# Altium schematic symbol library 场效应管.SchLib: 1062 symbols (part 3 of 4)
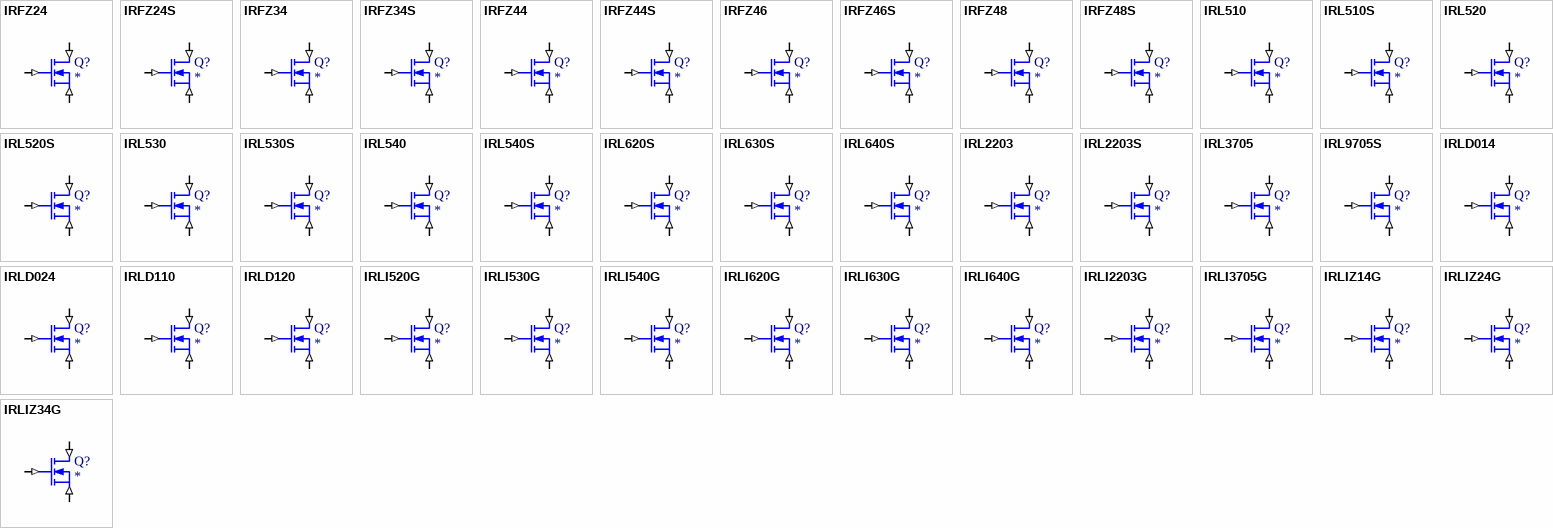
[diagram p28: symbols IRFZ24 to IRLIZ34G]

## IRL630S
designator Q?
N-Channel MOSFET
simulation model IRL630S (SUBCKT)
pins: 1 D (in), 2 G (in), 3 S (in)
1 alternate drawing of the same symbol

## IRL640S
designator Q?
N-Channel MOSFET
simulation model IRL640S (SUBCKT)
pins: 1 D (in), 2 G (in), 3 S (in)
1 alternate drawing of the same symbol

## IRL2203
designator Q?
N-Channel MOSFET
simulation model IRL2203 (SUBCKT)
pins: 1 D (in), 2 G (in), 3 S (in)
1 alternate drawing of the same symbol

## IRL2203S
designator Q?
N-Channel MOSFET
simulation model IRL2203S (SUBCKT)
pins: 1 D (in), 2 G (in), 3 S (in)
1 alternate drawing of the same symbol

## IRL3705
designator Q?
N-Channel MOSFET
simulation model IRL3705 (SUBCKT)
pins: 1 D (in), 2 G (in), 3 S (in)
1 alternate drawing of the same symbol

## IRL9705S
designator Q?
N-Channel MOSFET
simulation model IRL9705S (SUBCKT)
pins: 1 D (in), 2 G (in), 3 S (in)
1 alternate drawing of the same symbol

## IRLD014
designator Q?
N-Channel MOSFET
simulation model IRLD014 (SUBCKT)
pins: 1 D (in), 2 G (in), 3 S (in)
1 alternate drawing of the same symbol

## IRLD024
designator Q?
N-Channel MOSFET
simulation model IRLD024 (SUBCKT)
pins: 1 D (in), 2 G (in), 3 S (in)
1 alternate drawing of the same symbol

## IRLD110
designator Q?
N-Channel MOSFET
simulation model IRLD110 (SUBCKT)
pins: 1 D (in), 2 G (in), 3 S (in)
1 alternate drawing of the same symbol

## IRLD120
designator Q?
N-Channel MOSFET
simulation model IRLD120 (SUBCKT)
pins: 1 D (in), 2 G (in), 3 S (in)
1 alternate drawing of the same symbol

## IRLI520G
designator Q?
N-Channel MOSFET
simulation model IRLI520G (SUBCKT)
pins: 1 D (in), 2 G (in), 3 S (in)
1 alternate drawing of the same symbol

## IRLI530G
designator Q?
N-Channel MOSFET
simulation model IRLI530G (SUBCKT)
pins: 1 D (in), 2 G (in), 3 S (in)
1 alternate drawing of the same symbol

## IRLI540G
designator Q?
N-Channel MOSFET
simulation model IRLI540G (SUBCKT)
pins: 1 D (in), 2 G (in), 3 S (in)
1 alternate drawing of the same symbol

## IRLI620G
designator Q?
N-Channel MOSFET
simulation model IRLI620G (SUBCKT)
pins: 1 D (in), 2 G (in), 3 S (in)
1 alternate drawing of the same symbol

## IRLI630G
designator Q?
N-Channel MOSFET
simulation model IRLI630G (SUBCKT)
pins: 1 D (in), 2 G (in), 3 S (in)
1 alternate drawing of the same symbol

## IRLI640G
designator Q?
N-Channel MOSFET
simulation model IRLI640G (SUBCKT)
pins: 1 D (in), 2 G (in), 3 S (in)
1 alternate drawing of the same symbol

## IRLI2203G
designator Q?
N-Channel MOSFET
simulation model IRLI2203G (SUBCKT)
pins: 1 D (in), 2 G (in), 3 S (in)
1 alternate drawing of the same symbol

## IRLI3705G
designator Q?
N-Channel MOSFET
simulation model IRLI3705G (SUBCKT)
pins: 1 D (in), 2 G (in), 3 S (in)
1 alternate drawing of the same symbol

## IRLIZ14G
designator Q?
N-Channel MOSFET
simulation model IRLIZ14G (SUBCKT)
pins: 1 D (in), 2 G (in), 3 S (in)
1 alternate drawing of the same symbol

## IRLIZ24G
designator Q?
N-Channel MOSFET
simulation model IRLIZ24G (SUBCKT)
pins: 1 D (in), 2 G (in), 3 S (in)
1 alternate drawing of the same symbol

## IRLIZ34G
designator Q?
N-Channel MOSFET
simulation model IRLIZ34G (SUBCKT)
pins: 1 D (in), 2 G (in), 3 S (in)
1 alternate drawing of the same symbol

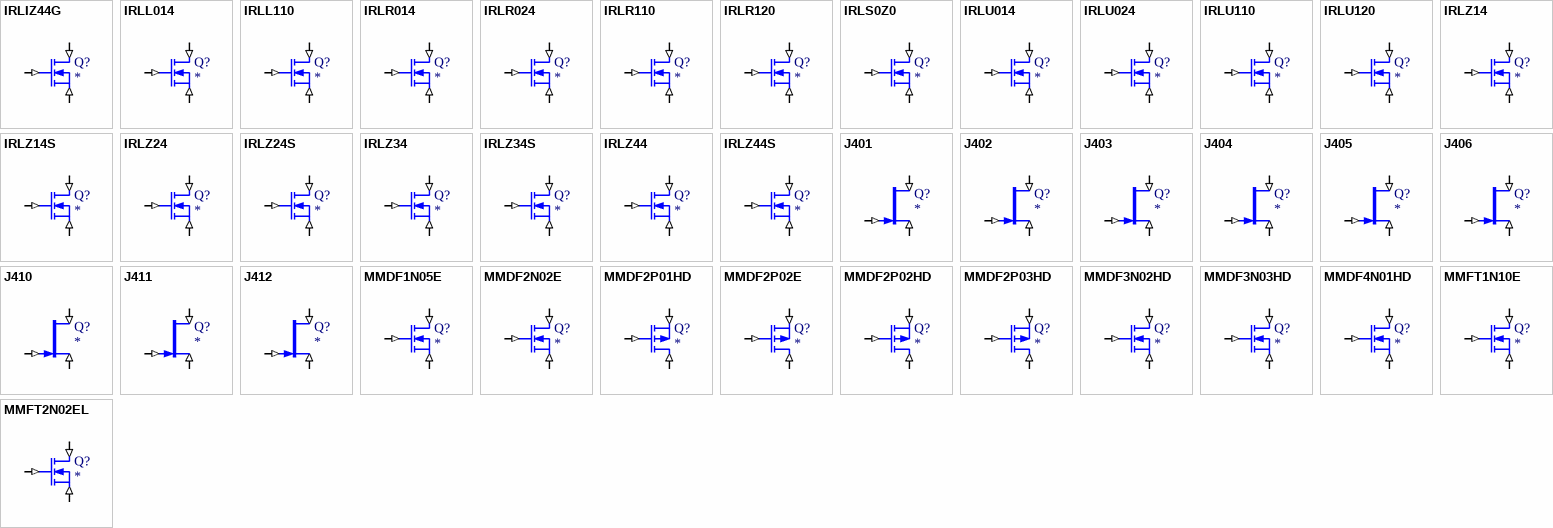
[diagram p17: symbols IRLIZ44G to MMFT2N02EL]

## IRLIZ44G
designator Q?
N-Channel MOSFET
simulation model IRLIZ44G (SUBCKT)
pins: 1 D (in), 2 G (in), 3 S (in)
1 alternate drawing of the same symbol

## IRLL014
designator Q?
N-Channel MOSFET
simulation model IRLL014 (SUBCKT)
pins: 1 D (in), 2 G (in), 3 S (in)
1 alternate drawing of the same symbol

## IRLL110
designator Q?
N-Channel MOSFET
simulation model IRLL110 (SUBCKT)
pins: 1 D (in), 2 G (in), 3 S (in)
1 alternate drawing of the same symbol

## IRLR014
designator Q?
N-Channel MOSFET
simulation model IRLR014 (SUBCKT)
pins: 1 D (in), 2 G (in), 3 S (in)
1 alternate drawing of the same symbol

## IRLR024
designator Q?
N-Channel MOSFET
simulation model IRLR024 (SUBCKT)
pins: 1 D (in), 2 G (in), 3 S (in)
1 alternate drawing of the same symbol

## IRLR110
designator Q?
N-Channel MOSFET
simulation model IRLR110 (SUBCKT)
pins: 1 D (in), 2 G (in), 3 S (in)
1 alternate drawing of the same symbol

## IRLR120
designator Q?
N-Channel MOSFET
simulation model IRLR120 (SUBCKT)
pins: 1 D (in), 2 G (in), 3 S (in)
1 alternate drawing of the same symbol

## IRLS0Z0
designator Q?
N-Channel MOSFET
simulation model IRLS0Z0 (SUBCKT)
pins: 1 D (in), 2 G (in), 3 S (in)
1 alternate drawing of the same symbol

## IRLU014
designator Q?
N-Channel MOSFET
simulation model IRLU014 (SUBCKT)
pins: 1 D (in), 2 G (in), 3 S (in)
1 alternate drawing of the same symbol

## IRLU024
designator Q?
N-Channel MOSFET
simulation model IRLU024 (SUBCKT)
pins: 1 D (in), 2 G (in), 3 S (in)
1 alternate drawing of the same symbol

## IRLU110
designator Q?
N-Channel MOSFET
simulation model IRLU110 (SUBCKT)
pins: 1 D (in), 2 G (in), 3 S (in)
1 alternate drawing of the same symbol

## IRLU120
designator Q?
N-Channel MOSFET
simulation model IRLU120 (SUBCKT)
pins: 1 D (in), 2 G (in), 3 S (in)
1 alternate drawing of the same symbol

## IRLZ14
designator Q?
N-Channel MOSFET
simulation model IRLZ14 (SUBCKT)
pins: 1 D (in), 2 G (in), 3 S (in)
1 alternate drawing of the same symbol

## IRLZ14S
designator Q?
N-Channel MOSFET
simulation model IRLZ14S (SUBCKT)
pins: 1 D (in), 2 G (in), 3 S (in)
1 alternate drawing of the same symbol

## IRLZ24
designator Q?
N-Channel MOSFET
simulation model IRLZ24 (SUBCKT)
pins: 1 D (in), 2 G (in), 3 S (in)
1 alternate drawing of the same symbol

## IRLZ24S
designator Q?
N-Channel MOSFET
simulation model IRLZ24S (SUBCKT)
pins: 1 D (in), 2 G (in), 3 S (in)
1 alternate drawing of the same symbol

## IRLZ34
designator Q?
N-Channel MOSFET
simulation model IRLZ34 (SUBCKT)
pins: 1 D (in), 2 G (in), 3 S (in)
1 alternate drawing of the same symbol

## IRLZ34S
designator Q?
N-Channel MOSFET
simulation model IRLZ34S (SUBCKT)
pins: 1 D (in), 2 G (in), 3 S (in)
1 alternate drawing of the same symbol

## IRLZ44
designator Q?
N-Channel MOSFET
simulation model IRLZ44 (SUBCKT)
pins: 1 D (in), 2 G (in), 3 S (in)
1 alternate drawing of the same symbol

## IRLZ44S
designator Q?
N-Channel MOSFET
simulation model IRLZ44S (SUBCKT)
pins: 1 D (in), 2 G (in), 3 S (in)
1 alternate drawing of the same symbol

## J401
designator Q?
N-Channel JFET
simulation model J401 (NJFET)
pins: 1 D (in), 2 G (in), 3 S (in)
1 alternate drawing of the same symbol

## J402
designator Q?
N-Channel JFET
simulation model J402 (NJFET)
pins: 1 D (in), 2 G (in), 3 S (in)
1 alternate drawing of the same symbol

## J403
designator Q?
N-Channel JFET
simulation model J403 (NJFET)
pins: 1 D (in), 2 G (in), 3 S (in)
1 alternate drawing of the same symbol

## J404
designator Q?
N-Channel JFET
simulation model J404 (NJFET)
pins: 1 D (in), 2 G (in), 3 S (in)
1 alternate drawing of the same symbol

## J405
designator Q?
N-Channel JFET
simulation model J405 (NJFET)
pins: 1 D (in), 2 G (in), 3 S (in)
1 alternate drawing of the same symbol

## J406
designator Q?
N-Channel JFET
simulation model J406 (NJFET)
pins: 1 D (in), 2 G (in), 3 S (in)
1 alternate drawing of the same symbol

## J410
designator Q?
N-Channel JFET
simulation model J410 (NJFET)
pins: 1 D (in), 2 G (in), 3 S (in)
1 alternate drawing of the same symbol

## J411
designator Q?
N-Channel JFET
simulation model J411 (NJFET)
pins: 1 D (in), 2 G (in), 3 S (in)
1 alternate drawing of the same symbol

## J412
designator Q?
N-Channel JFET
simulation model J412 (NJFET)
pins: 1 D (in), 2 G (in), 3 S (in)
1 alternate drawing of the same symbol

## MMDF1N05E
designator Q?
N-Channel MOSFET
simulation model MMDF1N05E (SUBCKT)
pins: 1 D (in), 2 G (in), 3 S (in)
1 alternate drawing of the same symbol

## MMDF2N02E
designator Q?
N-Channel MOSFET
simulation model MMDF2N02E (SUBCKT)
pins: 1 D (in), 2 G (in), 3 S (in)
1 alternate drawing of the same symbol

## MMDF2P01HD
designator Q?
P-Channel MOSFET
simulation model MMDF2P01HD (SUBCKT)
pins: 1 D (in), 2 G (in), 3 S (in)
1 alternate drawing of the same symbol

## MMDF2P02E
designator Q?
P-Channel MOSFET
simulation model MMDF2P02E (SUBCKT)
pins: 1 D (in), 2 G (in), 3 S (in)
1 alternate drawing of the same symbol

## MMDF2P02HD
designator Q?
P-Channel MOSFET
simulation model MMDF2P02HD (SUBCKT)
pins: 1 D (in), 2 G (in), 3 S (in)
1 alternate drawing of the same symbol

## MMDF2P03HD
designator Q?
P-Channel MOSFET
simulation model MMDF2P03HD (SUBCKT)
pins: 1 D (in), 2 G (in), 3 S (in)
1 alternate drawing of the same symbol

## MMDF3N02HD
designator Q?
N-Channel MOSFET
simulation model MMDF3N02HD (SUBCKT)
pins: 1 D (in), 2 G (in), 3 S (in)
1 alternate drawing of the same symbol

## MMDF3N03HD
designator Q?
N-Channel MOSFET
simulation model MMDF3N03HD (SUBCKT)
pins: 1 D (in), 2 G (in), 3 S (in)
1 alternate drawing of the same symbol

## MMDF4N01HD
designator Q?
N-Channel MOSFET
simulation model MMDF4N01HD (SUBCKT)
pins: 1 D (in), 2 G (in), 3 S (in)
1 alternate drawing of the same symbol

## MMFT1N10E
designator Q?
N-Channel MOSFET
simulation model MMFT1N10E (SUBCKT)
pins: 1 D (in), 2 G (in), 3 S (in)
1 alternate drawing of the same symbol

## MMFT2N02EL
designator Q?
N-Channel MOSFET
simulation model MMFT2N02EL (SUBCKT)
pins: 1 D (in), 2 G (in), 3 S (in)
1 alternate drawing of the same symbol

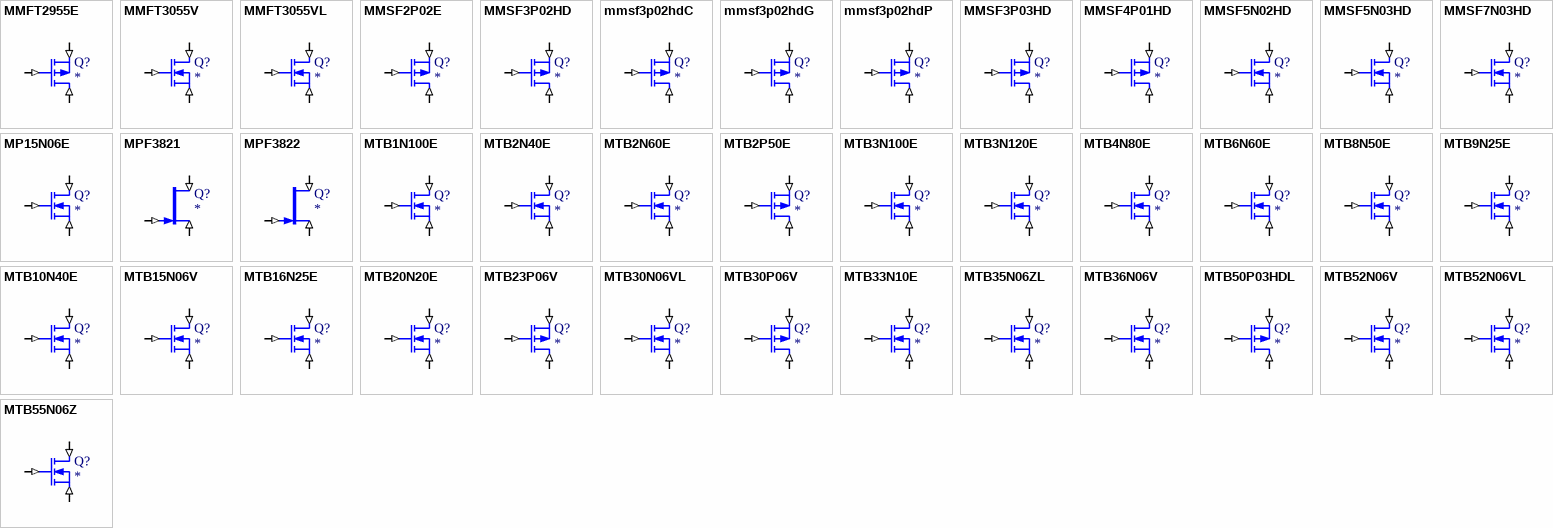
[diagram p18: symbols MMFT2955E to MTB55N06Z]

## MMFT2955E
designator Q?
P-Channel MOSFET
simulation model MMFT2955E (SUBCKT)
pins: 1 D (in), 2 G (in), 3 S (in)
1 alternate drawing of the same symbol

## MMFT3055V
designator Q?
N-Channel MOSFET
simulation model MMFT3055V (SUBCKT)
pins: 1 D (in), 2 G (in), 3 S (in)
1 alternate drawing of the same symbol

## MMFT3055VL
designator Q?
N-Channel MOSFET
simulation model MMFT3055VL (SUBCKT)
pins: 1 D (in), 2 G (in), 3 S (in)
1 alternate drawing of the same symbol

## MMSF2P02E
designator Q?
P-Channel MOSFET
simulation model MMSF2P02E (SUBCKT)
pins: 1 D (in), 2 G (in), 3 S (in)
1 alternate drawing of the same symbol

## MMSF3P02HD
designator Q?
P-Channel MOSFET
simulation model MMSF3P02HD (SUBCKT)
pins: 1 D (in), 2 G (in), 3 S (in)
1 alternate drawing of the same symbol

## mmsf3p02hdC
designator Q?
P-Channel MOSFET
simulation model mmsf3p02hdC (SUBCKT)
pins: 1 D (in), 2 G (in), 3 S (in)
1 alternate drawing of the same symbol

## mmsf3p02hdG
designator Q?
P-Channel MOSFET
simulation model mmsf3p02hdG (SUBCKT)
pins: 1 D (in), 2 G (in), 3 S (in)
1 alternate drawing of the same symbol

## mmsf3p02hdP
designator Q?
P-Channel MOSFET
simulation model mmsf3p02hdP (SUBCKT)
pins: 1 D (in), 2 G (in), 3 S (in)
1 alternate drawing of the same symbol

## MMSF3P03HD
designator Q?
P-Channel MOSFET
simulation model MMSF3P03HD (SUBCKT)
pins: 1 D (in), 2 G (in), 3 S (in)
1 alternate drawing of the same symbol

## MMSF4P01HD
designator Q?
P-Channel MOSFET
simulation model MMSF4P01HD (SUBCKT)
pins: 1 D (in), 2 G (in), 3 S (in)
1 alternate drawing of the same symbol

## MMSF5N02HD
designator Q?
N-Channel MOSFET
simulation model MMSF5N02HD (SUBCKT)
pins: 1 D (in), 2 G (in), 3 S (in)
1 alternate drawing of the same symbol

## MMSF5N03HD
designator Q?
N-Channel MOSFET
simulation model MMSF5N03HD (SUBCKT)
pins: 1 D (in), 2 G (in), 3 S (in)
1 alternate drawing of the same symbol

## MMSF7N03HD
designator Q?
N-Channel MOSFET
simulation model MMSF7N03HD (SUBCKT)
pins: 1 D (in), 2 G (in), 3 S (in)
1 alternate drawing of the same symbol

## MP15N06E
designator Q?
N-Channel MOSFET
simulation model MP15N06E (SUBCKT)
pins: 1 D (in), 2 G (in), 3 S (in)
1 alternate drawing of the same symbol

## MPF3821
designator Q?
N-Channel JFET
simulation model MPF3821 (NJFET)
pins: 1 D (in), 2 G (in), 3 S (in)
1 alternate drawing of the same symbol

## MPF3822
designator Q?
N-Channel JFET
simulation model MPF3822 (NJFET)
pins: 1 D (in), 2 G (in), 3 S (in)
1 alternate drawing of the same symbol

## MTB1N100E
designator Q?
N-Channel MOSFET
simulation model MTB1N100E (SUBCKT)
pins: 1 D (in), 2 G (in), 3 S (in)
1 alternate drawing of the same symbol

## MTB2N40E
designator Q?
N-Channel MOSFET
simulation model MTB2N40E (SUBCKT)
pins: 1 D (in), 2 G (in), 3 S (in)
1 alternate drawing of the same symbol

## MTB2N60E
designator Q?
N-Channel MOSFET
simulation model MTB2N60E (SUBCKT)
pins: 1 D (in), 2 G (in), 3 S (in)
1 alternate drawing of the same symbol

## MTB2P50E
designator Q?
P-Channel MOSFET
simulation model MTB2P50E (SUBCKT)
pins: 1 D (in), 2 G (in), 3 S (in)
1 alternate drawing of the same symbol

## MTB3N100E
designator Q?
N-Channel MOSFET
simulation model MTB3N100E (SUBCKT)
pins: 1 D (in), 2 G (in), 3 S (in)
1 alternate drawing of the same symbol

## MTB3N120E
designator Q?
N-Channel MOSFET
simulation model MTB3N120E (SUBCKT)
pins: 1 D (in), 2 G (in), 3 S (in)
1 alternate drawing of the same symbol

## MTB4N80E
designator Q?
N-Channel MOSFET
simulation model MTB4N80E (SUBCKT)
pins: 1 D (in), 2 G (in), 3 S (in)
1 alternate drawing of the same symbol

## MTB6N60E
designator Q?
N-Channel MOSFET
simulation model MTB6N60E (SUBCKT)
pins: 1 D (in), 2 G (in), 3 S (in)
1 alternate drawing of the same symbol

## MTB8N50E
designator Q?
N-Channel MOSFET
simulation model MTB8N50E (SUBCKT)
pins: 1 D (in), 2 G (in), 3 S (in)
1 alternate drawing of the same symbol

## MTB9N25E
designator Q?
N-Channel MOSFET
simulation model MTB9N25E (SUBCKT)
pins: 1 D (in), 2 G (in), 3 S (in)
1 alternate drawing of the same symbol

## MTB10N40E
designator Q?
N-Channel MOSFET
simulation model MTB10N40E (SUBCKT)
pins: 1 D (in), 2 G (in), 3 S (in)
1 alternate drawing of the same symbol

## MTB15N06V
designator Q?
N-Channel MOSFET
simulation model MTB15N06V (SUBCKT)
pins: 1 D (in), 2 G (in), 3 S (in)
1 alternate drawing of the same symbol

## MTB16N25E
designator Q?
N-Channel MOSFET
simulation model MTB16N25E (SUBCKT)
pins: 1 D (in), 2 G (in), 3 S (in)
1 alternate drawing of the same symbol

## MTB20N20E
designator Q?
N-Channel MOSFET
simulation model MTB20N20E (SUBCKT)
pins: 1 D (in), 2 G (in), 3 S (in)
1 alternate drawing of the same symbol

## MTB23P06V
designator Q?
P-Channel MOSFET
simulation model MTB23P06V (SUBCKT)
pins: 1 D (in), 2 G (in), 3 S (in)
1 alternate drawing of the same symbol

## MTB30N06VL
designator Q?
N-Channel MOSFET
simulation model MTB30N06VL (SUBCKT)
pins: 1 D (in), 2 G (in), 3 S (in)
1 alternate drawing of the same symbol

## MTB30P06V
designator Q?
P-Channel MOSFET
simulation model MTB30P06V (SUBCKT)
pins: 1 D (in), 2 G (in), 3 S (in)
1 alternate drawing of the same symbol

## MTB33N10E
designator Q?
N-Channel MOSFET
simulation model MTB33N10E (SUBCKT)
pins: 1 D (in), 2 G (in), 3 S (in)
1 alternate drawing of the same symbol

## MTB35N06ZL
designator Q?
N-Channel MOSFET
simulation model MTB35N06ZL (SUBCKT)
pins: 1 D (in), 2 G (in), 3 S (in)
1 alternate drawing of the same symbol

## MTB36N06V
designator Q?
N-Channel MOSFET
simulation model MTB36N06V (SUBCKT)
pins: 1 D (in), 2 G (in), 3 S (in)
1 alternate drawing of the same symbol

## MTB50P03HDL
designator Q?
P-Channel MOSFET
simulation model MTB50P03HDL (SUBCKT)
pins: 1 D (in), 2 G (in), 3 S (in)
1 alternate drawing of the same symbol

## MTB52N06V
designator Q?
N-Channel MOSFET
simulation model MTB52N06V (SUBCKT)
pins: 1 D (in), 2 G (in), 3 S (in)
1 alternate drawing of the same symbol

## MTB52N06VL
designator Q?
N-Channel MOSFET
simulation model MTB52N06VL (SUBCKT)
pins: 1 D (in), 2 G (in), 3 S (in)
1 alternate drawing of the same symbol

## MTB55N06Z
designator Q?
N-Channel MOSFET
simulation model MTB55N06Z (SUBCKT)
pins: 1 D (in), 2 G (in), 3 S (in)
1 alternate drawing of the same symbol

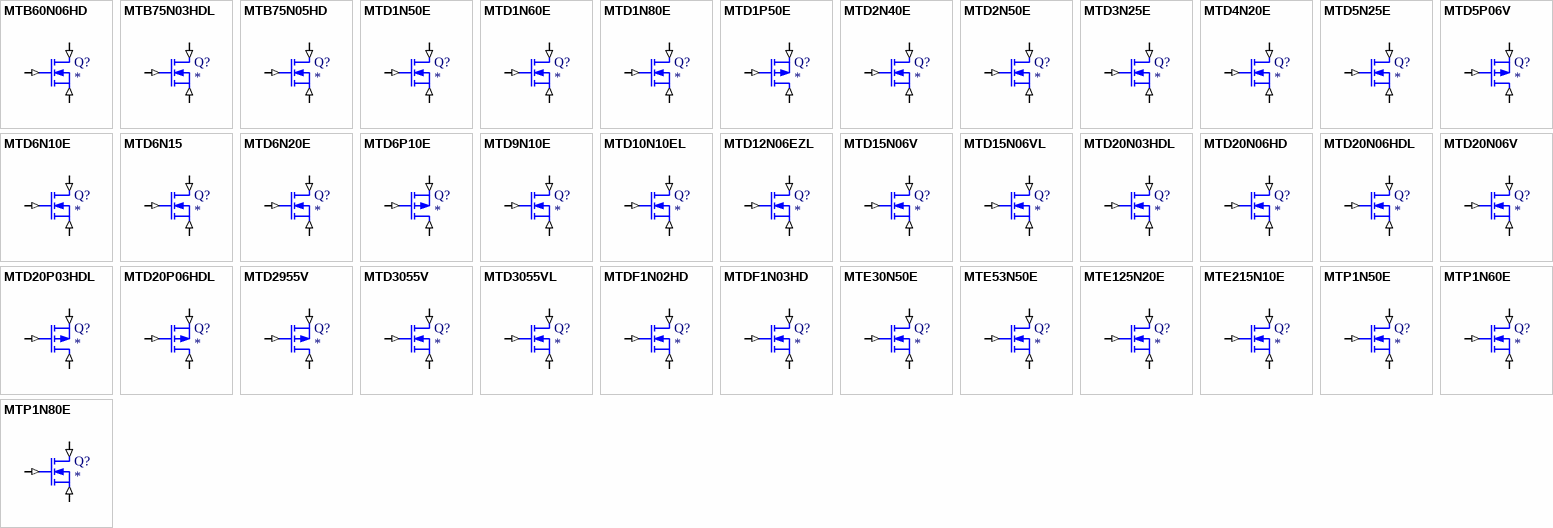
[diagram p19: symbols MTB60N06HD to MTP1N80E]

## MTB60N06HD
designator Q?
N-Channel MOSFET
simulation model MTB60N06HD (SUBCKT)
pins: 1 D (in), 2 G (in), 3 S (in)
1 alternate drawing of the same symbol

## MTB75N03HDL
designator Q?
N-Channel MOSFET
simulation model MTB75N03HDL (SUBCKT)
pins: 1 D (in), 2 G (in), 3 S (in)
1 alternate drawing of the same symbol

## MTB75N05HD
designator Q?
N-Channel MOSFET
simulation model MTB75N05HD (SUBCKT)
pins: 1 D (in), 2 G (in), 3 S (in)
1 alternate drawing of the same symbol

## MTD1N50E
designator Q?
N-Channel MOSFET
simulation model MTD1N50E (SUBCKT)
pins: 1 D (in), 2 G (in), 3 S (in)
1 alternate drawing of the same symbol

## MTD1N60E
designator Q?
N-Channel MOSFET
simulation model MTD1N60E (SUBCKT)
pins: 1 D (in), 2 G (in), 3 S (in)
1 alternate drawing of the same symbol

## MTD1N80E
designator Q?
N-Channel MOSFET
simulation model MTD1N80E (SUBCKT)
pins: 1 D (in), 2 G (in), 3 S (in)
1 alternate drawing of the same symbol

## MTD1P50E
designator Q?
P-Channel MOSFET
simulation model MTD1P50E (SUBCKT)
pins: 1 D (in), 2 G (in), 3 S (in)
1 alternate drawing of the same symbol

## MTD2N40E
designator Q?
N-Channel MOSFET
simulation model MTD2N40E (SUBCKT)
pins: 1 D (in), 2 G (in), 3 S (in)
1 alternate drawing of the same symbol

## MTD2N50E
designator Q?
N-Channel MOSFET
simulation model MTD2N50E (SUBCKT)
pins: 1 D (in), 2 G (in), 3 S (in)
1 alternate drawing of the same symbol

## MTD3N25E
designator Q?
N-Channel MOSFET
simulation model MTD3N25E (SUBCKT)
pins: 1 D (in), 2 G (in), 3 S (in)
1 alternate drawing of the same symbol

## MTD4N20E
designator Q?
N-Channel MOSFET
simulation model MTD4N20E (SUBCKT)
pins: 1 D (in), 2 G (in), 3 S (in)
1 alternate drawing of the same symbol

## MTD5N25E
designator Q?
N-Channel MOSFET
simulation model MTD5N25E (SUBCKT)
pins: 1 D (in), 2 G (in), 3 S (in)
1 alternate drawing of the same symbol

## MTD5P06V
designator Q?
P-Channel MOSFET
simulation model MTD5P06V (SUBCKT)
pins: 1 D (in), 2 G (in), 3 S (in)
1 alternate drawing of the same symbol

## MTD6N10E
designator Q?
N-Channel MOSFET
simulation model MTD6N10E (SUBCKT)
pins: 1 D (in), 2 G (in), 3 S (in)
1 alternate drawing of the same symbol

## MTD6N15
designator Q?
N-Channel MOSFET
simulation model MTD6N15 (SUBCKT)
pins: 1 D (in), 2 G (in), 3 S (in)
1 alternate drawing of the same symbol

## MTD6N20E
designator Q?
N-Channel MOSFET
simulation model MTD6N20E (SUBCKT)
pins: 1 D (in), 2 G (in), 3 S (in)
1 alternate drawing of the same symbol

## MTD6P10E
designator Q?
P-Channel MOSFET
simulation model MTD6P10E (SUBCKT)
pins: 1 D (in), 2 G (in), 3 S (in)
1 alternate drawing of the same symbol

## MTD9N10E
designator Q?
N-Channel MOSFET
simulation model MTD9N10E (SUBCKT)
pins: 1 D (in), 2 G (in), 3 S (in)
1 alternate drawing of the same symbol

## MTD10N10EL
designator Q?
N-Channel MOSFET
simulation model MTD10N10EL (SUBCKT)
pins: 1 D (in), 2 G (in), 3 S (in)
1 alternate drawing of the same symbol

## MTD12N06EZL
designator Q?
N-Channel MOSFET
simulation model MTD12N06EZL (SUBCKT)
pins: 1 D (in), 2 G (in), 3 S (in)
1 alternate drawing of the same symbol

## MTD15N06V
designator Q?
N-Channel MOSFET
simulation model MTD15N06V (SUBCKT)
pins: 1 D (in), 2 G (in), 3 S (in)
1 alternate drawing of the same symbol

## MTD15N06VL
designator Q?
N-Channel MOSFET
simulation model MTD15N06VL (SUBCKT)
pins: 1 D (in), 2 G (in), 3 S (in)
1 alternate drawing of the same symbol

## MTD20N03HDL
designator Q?
N-Channel MOSFET
simulation model MTD20N03HDL (SUBCKT)
pins: 1 D (in), 2 G (in), 3 S (in)
1 alternate drawing of the same symbol

## MTD20N06HD
designator Q?
N-Channel MOSFET
simulation model MTD20N06HD (SUBCKT)
pins: 1 D (in), 2 G (in), 3 S (in)
1 alternate drawing of the same symbol

## MTD20N06HDL
designator Q?
N-Channel MOSFET
simulation model MTD20N06HDL (SUBCKT)
pins: 1 D (in), 2 G (in), 3 S (in)
1 alternate drawing of the same symbol

## MTD20N06V
designator Q?
N-Channel MOSFET
simulation model MTD20N06V (SUBCKT)
pins: 1 D (in), 2 G (in), 3 S (in)
1 alternate drawing of the same symbol

## MTD20P03HDL
designator Q?
P-Channel MOSFET
simulation model MTD20P03HDL (SUBCKT)
pins: 1 D (in), 2 G (in), 3 S (in)
1 alternate drawing of the same symbol

## MTD20P06HDL
designator Q?
P-Channel MOSFET
simulation model MTD20P06HDL (SUBCKT)
pins: 1 D (in), 2 G (in), 3 S (in)
1 alternate drawing of the same symbol

## MTD2955V
designator Q?
P-Channel MOSFET
simulation model MTD2955V (SUBCKT)
pins: 1 D (in), 2 G (in), 3 S (in)
1 alternate drawing of the same symbol

## MTD3055V
designator Q?
N-Channel MOSFET
simulation model MTD3055V (SUBCKT)
pins: 1 D (in), 2 G (in), 3 S (in)
1 alternate drawing of the same symbol

## MTD3055VL
designator Q?
N-Channel MOSFET
simulation model MTD3055VL (SUBCKT)
pins: 1 D (in), 2 G (in), 3 S (in)
1 alternate drawing of the same symbol

## MTDF1N02HD
designator Q?
N-Channel MOSFET
simulation model MTDF1N02HD (SUBCKT)
pins: 1 D (in), 2 G (in), 3 S (in)
1 alternate drawing of the same symbol

## MTDF1N03HD
designator Q?
N-Channel MOSFET
simulation model MTDF1N03HD (SUBCKT)
pins: 1 D (in), 2 G (in), 3 S (in)
1 alternate drawing of the same symbol

## MTE30N50E
designator Q?
N-Channel MOSFET
simulation model MTE30N50E (SUBCKT)
pins: 1 D (in), 2 G (in), 3 S (in)
1 alternate drawing of the same symbol

## MTE53N50E
designator Q?
N-Channel MOSFET
simulation model MTE53N50E (SUBCKT)
pins: 1 D (in), 2 G (in), 3 S (in)
1 alternate drawing of the same symbol

## MTE125N20E
designator Q?
N-Channel MOSFET
simulation model MTE125N20E (SUBCKT)
pins: 1 D (in), 2 G (in), 3 S (in)
1 alternate drawing of the same symbol

## MTE215N10E
designator Q?
N-Channel MOSFET
simulation model MTE215N10E (SUBCKT)
pins: 1 D (in), 2 G (in), 3 S (in)
1 alternate drawing of the same symbol

## MTP1N50E
designator Q?
N-Channel MOSFET
simulation model MTP1N50E (SUBCKT)
pins: 1 D (in), 2 G (in), 3 S (in)
1 alternate drawing of the same symbol

## MTP1N60E
designator Q?
N-Channel MOSFET
simulation model MTP1N60E (SUBCKT)
pins: 1 D (in), 2 G (in), 3 S (in)
1 alternate drawing of the same symbol

## MTP1N80E
designator Q?
N-Channel MOSFET
simulation model MTP1N80E (SUBCKT)
pins: 1 D (in), 2 G (in), 3 S (in)
1 alternate drawing of the same symbol

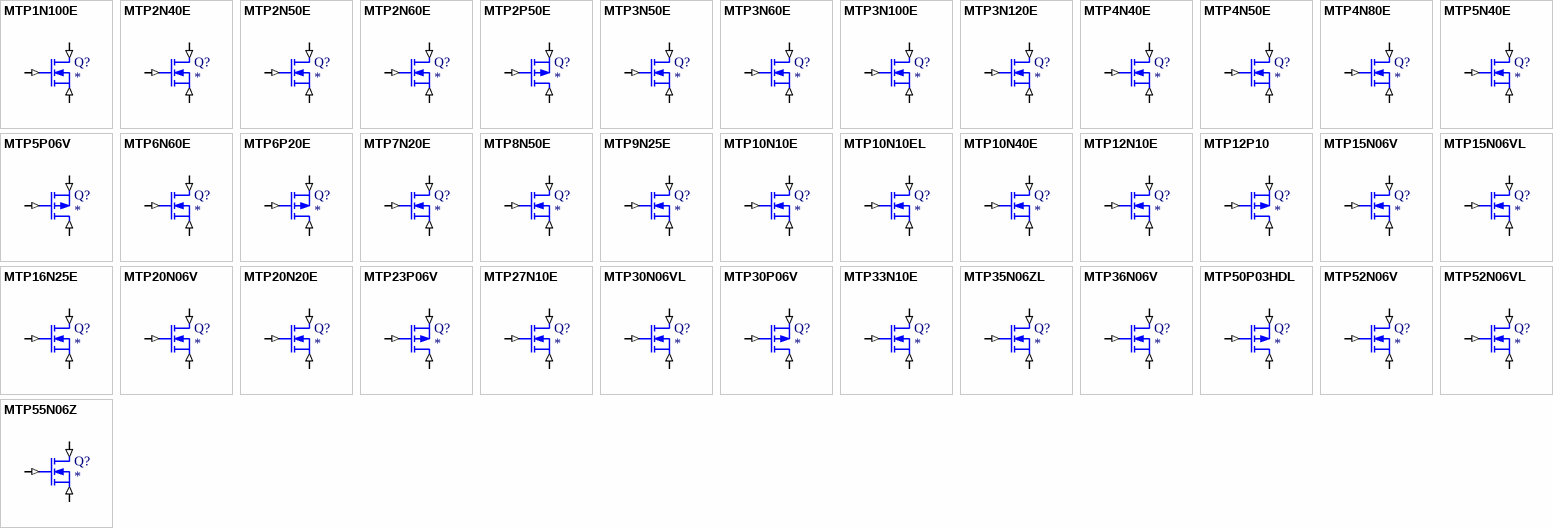
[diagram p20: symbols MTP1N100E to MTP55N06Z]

## MTP1N100E
designator Q?
N-Channel MOSFET
simulation model MTP1N100E (SUBCKT)
pins: 1 D (in), 2 G (in), 3 S (in)
1 alternate drawing of the same symbol

## MTP2N40E
designator Q?
N-Channel MOSFET
simulation model MTP2N40E (SUBCKT)
pins: 1 D (in), 2 G (in), 3 S (in)
1 alternate drawing of the same symbol

## MTP2N50E
designator Q?
N-Channel MOSFET
simulation model MTP2N50E (SUBCKT)
pins: 1 D (in), 2 G (in), 3 S (in)
1 alternate drawing of the same symbol

## MTP2N60E
designator Q?
N-Channel MOSFET
simulation model MTP2N60E (SUBCKT)
pins: 1 D (in), 2 G (in), 3 S (in)
1 alternate drawing of the same symbol

## MTP2P50E
designator Q?
P-Channel MOSFET
simulation model MTP2P50E (SUBCKT)
pins: 1 D (in), 2 G (in), 3 S (in)
1 alternate drawing of the same symbol

## MTP3N50E
designator Q?
N-Channel MOSFET
simulation model MTP3N50E (SUBCKT)
pins: 1 D (in), 2 G (in), 3 S (in)
1 alternate drawing of the same symbol

## MTP3N60E
designator Q?
N-Channel MOSFET
simulation model MTP3N60E (SUBCKT)
pins: 1 D (in), 2 G (in), 3 S (in)
1 alternate drawing of the same symbol

## MTP3N100E
designator Q?
N-Channel MOSFET
simulation model MTP3N100E (SUBCKT)
pins: 1 D (in), 2 G (in), 3 S (in)
1 alternate drawing of the same symbol

## MTP3N120E
designator Q?
N-Channel MOSFET
simulation model MTP3N120E (SUBCKT)
pins: 1 D (in), 2 G (in), 3 S (in)
1 alternate drawing of the same symbol

## MTP4N40E
designator Q?
N-Channel MOSFET
simulation model MTP4N40E (SUBCKT)
pins: 1 D (in), 2 G (in), 3 S (in)
1 alternate drawing of the same symbol

## MTP4N50E
designator Q?
N-Channel MOSFET
simulation model MTP4N50E (SUBCKT)
pins: 1 D (in), 2 G (in), 3 S (in)
1 alternate drawing of the same symbol

## MTP4N80E
designator Q?
N-Channel MOSFET
simulation model MTP4N80E (SUBCKT)
pins: 1 D (in), 2 G (in), 3 S (in)
1 alternate drawing of the same symbol

## MTP5N40E
designator Q?
N-Channel MOSFET
simulation model MTP5N40E (SUBCKT)
pins: 1 D (in), 2 G (in), 3 S (in)
1 alternate drawing of the same symbol

## MTP5P06V
designator Q?
P-Channel MOSFET
simulation model MTP5P06V (SUBCKT)
pins: 1 D (in), 2 G (in), 3 S (in)
1 alternate drawing of the same symbol

## MTP6N60E
designator Q?
N-Channel MOSFET
simulation model MTP6N60E (SUBCKT)
pins: 1 D (in), 2 G (in), 3 S (in)
1 alternate drawing of the same symbol

## MTP6P20E
designator Q?
P-Channel MOSFET
simulation model MTP6P20E (SUBCKT)
pins: 1 D (in), 2 G (in), 3 S (in)
1 alternate drawing of the same symbol

## MTP7N20E
designator Q?
N-Channel MOSFET
simulation model MTP7N20E (SUBCKT)
pins: 1 D (in), 2 G (in), 3 S (in)
1 alternate drawing of the same symbol

## MTP8N50E
designator Q?
N-Channel MOSFET
simulation model MTP8N50E (SUBCKT)
pins: 1 D (in), 2 G (in), 3 S (in)
1 alternate drawing of the same symbol

## MTP9N25E
designator Q?
N-Channel MOSFET
simulation model MTP9N25E (SUBCKT)
pins: 1 D (in), 2 G (in), 3 S (in)
1 alternate drawing of the same symbol

## MTP10N10E
designator Q?
N-Channel MOSFET
simulation model MTP10N10E (SUBCKT)
pins: 1 D (in), 2 G (in), 3 S (in)
1 alternate drawing of the same symbol

## MTP10N10EL
designator Q?
N-Channel MOSFET
simulation model MTP10N10EL (SUBCKT)
pins: 1 D (in), 2 G (in), 3 S (in)
1 alternate drawing of the same symbol

## MTP10N40E
designator Q?
N-Channel MOSFET
simulation model MTP10N40E (SUBCKT)
pins: 1 D (in), 2 G (in), 3 S (in)
1 alternate drawing of the same symbol

## MTP12N10E
designator Q?
N-Channel MOSFET
simulation model MTP12N10E (SUBCKT)
pins: 1 D (in), 2 G (in), 3 S (in)
1 alternate drawing of the same symbol

## MTP12P10
designator Q?
P-Channel MOSFET
simulation model MTP12P10 (SUBCKT)
pins: 1 D (in), 2 G (in), 3 S (in)
1 alternate drawing of the same symbol

## MTP15N06V
designator Q?
N-Channel MOSFET
simulation model MTP15N06V (SUBCKT)
pins: 1 D (in), 2 G (in), 3 S (in)
1 alternate drawing of the same symbol

## MTP15N06VL
designator Q?
N-Channel MOSFET
simulation model MTP15N06VL (SUBCKT)
pins: 1 D (in), 2 G (in), 3 S (in)
1 alternate drawing of the same symbol

## MTP16N25E
designator Q?
N-Channel MOSFET
simulation model MTP16N25E (SUBCKT)
pins: 1 D (in), 2 G (in), 3 S (in)
1 alternate drawing of the same symbol

## MTP20N06V
designator Q?
N-Channel MOSFET
simulation model MTP20N06V (SUBCKT)
pins: 1 D (in), 2 G (in), 3 S (in)
1 alternate drawing of the same symbol

## MTP20N20E
designator Q?
N-Channel MOSFET
simulation model MTP20N20E (SUBCKT)
pins: 1 D (in), 2 G (in), 3 S (in)
1 alternate drawing of the same symbol

## MTP23P06V
designator Q?
P-Channel MOSFET
simulation model MTP23P06V (SUBCKT)
pins: 1 D (in), 2 G (in), 3 S (in)
1 alternate drawing of the same symbol

## MTP27N10E
designator Q?
N-Channel MOSFET
simulation model MTP27N10E (SUBCKT)
pins: 1 D (in), 2 G (in), 3 S (in)
1 alternate drawing of the same symbol

## MTP30N06VL
designator Q?
N-Channel MOSFET
simulation model MTP30N06VL (SUBCKT)
pins: 1 D (in), 2 G (in), 3 S (in)
1 alternate drawing of the same symbol

## MTP30P06V
designator Q?
P-Channel MOSFET
simulation model MTP30P06V (SUBCKT)
pins: 1 D (in), 2 G (in), 3 S (in)
1 alternate drawing of the same symbol

## MTP33N10E
designator Q?
N-Channel MOSFET
simulation model MTP33N10E (SUBCKT)
pins: 1 D (in), 2 G (in), 3 S (in)
1 alternate drawing of the same symbol

## MTP35N06ZL
designator Q?
N-Channel MOSFET
simulation model MTP35N06ZL (SUBCKT)
pins: 1 D (in), 2 G (in), 3 S (in)
1 alternate drawing of the same symbol

## MTP36N06V
designator Q?
N-Channel MOSFET
simulation model MTP36N06V (SUBCKT)
pins: 1 D (in), 2 G (in), 3 S (in)
1 alternate drawing of the same symbol

## MTP50P03HDL
designator Q?
P-Channel MOSFET
simulation model MTP50P03HDL (SUBCKT)
pins: 1 D (in), 2 G (in), 3 S (in)
1 alternate drawing of the same symbol

## MTP52N06V
designator Q?
N-Channel MOSFET
simulation model MTP52N06V (SUBCKT)
pins: 1 D (in), 2 G (in), 3 S (in)
1 alternate drawing of the same symbol

## MTP52N06VL
designator Q?
N-Channel MOSFET
simulation model MTP52N06VL (SUBCKT)
pins: 1 D (in), 2 G (in), 3 S (in)
1 alternate drawing of the same symbol

## MTP55N06Z
designator Q?
N-Channel MOSFET
simulation model MTP55N06Z (SUBCKT)
pins: 1 D (in), 2 G (in), 3 S (in)
1 alternate drawing of the same symbol

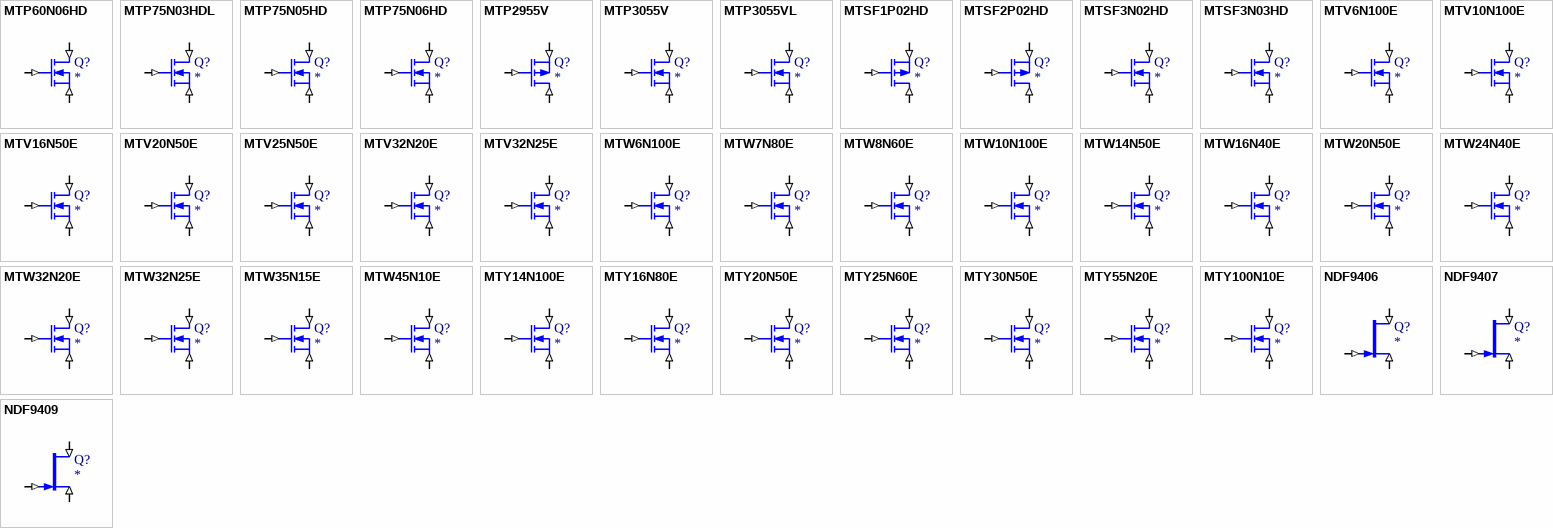
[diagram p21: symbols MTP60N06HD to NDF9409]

## MTP60N06HD
designator Q?
N-Channel MOSFET
simulation model MTP60N06HD (SUBCKT)
pins: 1 D (in), 2 G (in), 3 S (in)
1 alternate drawing of the same symbol

## MTP75N03HDL
designator Q?
N-Channel MOSFET
simulation model MTP75N03HDL (SUBCKT)
pins: 1 D (in), 2 G (in), 3 S (in)
1 alternate drawing of the same symbol

## MTP75N05HD
designator Q?
N-Channel MOSFET
simulation model MTP75N05HD (SUBCKT)
pins: 1 D (in), 2 G (in), 3 S (in)
1 alternate drawing of the same symbol

## MTP75N06HD
designator Q?
N-Channel MOSFET
simulation model MTP75N06HD (SUBCKT)
pins: 1 D (in), 2 G (in), 3 S (in)
1 alternate drawing of the same symbol

## MTP2955V
designator Q?
P-Channel MOSFET
simulation model MTP2955V (SUBCKT)
pins: 1 D (in), 2 G (in), 3 S (in)
1 alternate drawing of the same symbol

## MTP3055V
designator Q?
N-Channel MOSFET
simulation model MTP3055V (SUBCKT)
pins: 1 D (in), 2 G (in), 3 S (in)
1 alternate drawing of the same symbol

## MTP3055VL
designator Q?
N-Channel MOSFET
simulation model MTP3055VL (SUBCKT)
pins: 1 D (in), 2 G (in), 3 S (in)
1 alternate drawing of the same symbol

## MTSF1P02HD
designator Q?
P-Channel MOSFET
simulation model MTSF1P02HD (SUBCKT)
pins: 1 D (in), 2 G (in), 3 S (in)
1 alternate drawing of the same symbol

## MTSF2P02HD
designator Q?
P-Channel MOSFET
simulation model MTSF2P02HD (SUBCKT)
pins: 1 D (in), 2 G (in), 3 S (in)
1 alternate drawing of the same symbol

## MTSF3N02HD
designator Q?
N-Channel MOSFET
simulation model MTSF3N02HD (SUBCKT)
pins: 1 D (in), 2 G (in), 3 S (in)
1 alternate drawing of the same symbol

## MTSF3N03HD
designator Q?
N-Channel MOSFET
simulation model MTSF3N03HD (SUBCKT)
pins: 1 D (in), 2 G (in), 3 S (in)
1 alternate drawing of the same symbol

## MTV6N100E
designator Q?
N-Channel MOSFET
simulation model MTV6N100E (SUBCKT)
pins: 1 D (in), 2 G (in), 3 S (in)
1 alternate drawing of the same symbol

## MTV10N100E
designator Q?
N-Channel MOSFET
simulation model MTV10N100E (SUBCKT)
pins: 1 D (in), 2 G (in), 3 S (in)
1 alternate drawing of the same symbol

## MTV16N50E
designator Q?
N-Channel MOSFET
simulation model MTV16N50E (SUBCKT)
pins: 1 D (in), 2 G (in), 3 S (in)
1 alternate drawing of the same symbol

## MTV20N50E
designator Q?
N-Channel MOSFET
simulation model MTV20N50E (SUBCKT)
pins: 1 D (in), 2 G (in), 3 S (in)
1 alternate drawing of the same symbol

## MTV25N50E
designator Q?
N-Channel MOSFET
simulation model MTV25N50E (SUBCKT)
pins: 1 D (in), 2 G (in), 3 S (in)
1 alternate drawing of the same symbol

## MTV32N20E
designator Q?
N-Channel MOSFET
simulation model MTV32N20E (SUBCKT)
pins: 1 D (in), 2 G (in), 3 S (in)
1 alternate drawing of the same symbol

## MTV32N25E
designator Q?
N-Channel MOSFET
simulation model MTV32N25E (SUBCKT)
pins: 1 D (in), 2 G (in), 3 S (in)
1 alternate drawing of the same symbol

## MTW6N100E
designator Q?
N-Channel MOSFET
simulation model MTW6N100E (SUBCKT)
pins: 1 D (in), 2 G (in), 3 S (in)
1 alternate drawing of the same symbol

## MTW7N80E
designator Q?
N-Channel MOSFET
simulation model MTW7N80E (SUBCKT)
pins: 1 D (in), 2 G (in), 3 S (in)
1 alternate drawing of the same symbol

## MTW8N60E
designator Q?
N-Channel MOSFET
simulation model MTW8N60E (SUBCKT)
pins: 1 D (in), 2 G (in), 3 S (in)
1 alternate drawing of the same symbol

## MTW10N100E
designator Q?
N-Channel MOSFET
simulation model MTW10N100E (SUBCKT)
pins: 1 D (in), 2 G (in), 3 S (in)
1 alternate drawing of the same symbol

## MTW14N50E
designator Q?
N-Channel MOSFET
simulation model MTW14N50E (SUBCKT)
pins: 1 D (in), 2 G (in), 3 S (in)
1 alternate drawing of the same symbol

## MTW16N40E
designator Q?
N-Channel MOSFET
simulation model MTW16N40E (SUBCKT)
pins: 1 D (in), 2 G (in), 3 S (in)
1 alternate drawing of the same symbol

## MTW20N50E
designator Q?
N-Channel MOSFET
simulation model MTW20N50E (SUBCKT)
pins: 1 D (in), 2 G (in), 3 S (in)
1 alternate drawing of the same symbol

## MTW24N40E
designator Q?
N-Channel MOSFET
simulation model MTW24N40E (SUBCKT)
pins: 1 D (in), 2 G (in), 3 S (in)
1 alternate drawing of the same symbol

## MTW32N20E
designator Q?
N-Channel MOSFET
simulation model MTW32N20E (SUBCKT)
pins: 1 D (in), 2 G (in), 3 S (in)
1 alternate drawing of the same symbol

## MTW32N25E
designator Q?
N-Channel MOSFET
simulation model MTW32N25E (SUBCKT)
pins: 1 D (in), 2 G (in), 3 S (in)
1 alternate drawing of the same symbol

## MTW35N15E
designator Q?
N-Channel MOSFET
simulation model MTW35N15E (SUBCKT)
pins: 1 D (in), 2 G (in), 3 S (in)
1 alternate drawing of the same symbol

## MTW45N10E
designator Q?
N-Channel MOSFET
simulation model MTW45N10E (SUBCKT)
pins: 1 D (in), 2 G (in), 3 S (in)
1 alternate drawing of the same symbol

## MTY14N100E
designator Q?
N-Channel MOSFET
simulation model MTY14N100E (SUBCKT)
pins: 1 D (in), 2 G (in), 3 S (in)
1 alternate drawing of the same symbol

## MTY16N80E
designator Q?
N-Channel MOSFET
simulation model MTY16N80E (SUBCKT)
pins: 1 D (in), 2 G (in), 3 S (in)
1 alternate drawing of the same symbol

## MTY20N50E
designator Q?
N-Channel MOSFET
simulation model MTY20N50E (SUBCKT)
pins: 1 D (in), 2 G (in), 3 S (in)
1 alternate drawing of the same symbol

## MTY25N60E
designator Q?
N-Channel MOSFET
simulation model MTY25N60E (SUBCKT)
pins: 1 D (in), 2 G (in), 3 S (in)
1 alternate drawing of the same symbol

## MTY30N50E
designator Q?
N-Channel MOSFET
simulation model MTY30N50E (SUBCKT)
pins: 1 D (in), 2 G (in), 3 S (in)
1 alternate drawing of the same symbol

## MTY55N20E
designator Q?
N-Channel MOSFET
simulation model MTY55N20E (SUBCKT)
pins: 1 D (in), 2 G (in), 3 S (in)
1 alternate drawing of the same symbol

## MTY100N10E
designator Q?
N-Channel MOSFET
simulation model MTY100N10E (SUBCKT)
pins: 1 D (in), 2 G (in), 3 S (in)
1 alternate drawing of the same symbol

## NDF9406
designator Q?
N-Channel JFET
simulation model NDF9406 (NJFET)
pins: 1 D (in), 2 G (in), 3 S (in)
1 alternate drawing of the same symbol

## NDF9407
designator Q?
N-Channel JFET
simulation model NDF9407 (NJFET)
pins: 1 D (in), 2 G (in), 3 S (in)
1 alternate drawing of the same symbol

## NDF9409
designator Q?
N-Channel JFET
simulation model NDF9409 (NJFET)
pins: 1 D (in), 2 G (in), 3 S (in)
1 alternate drawing of the same symbol

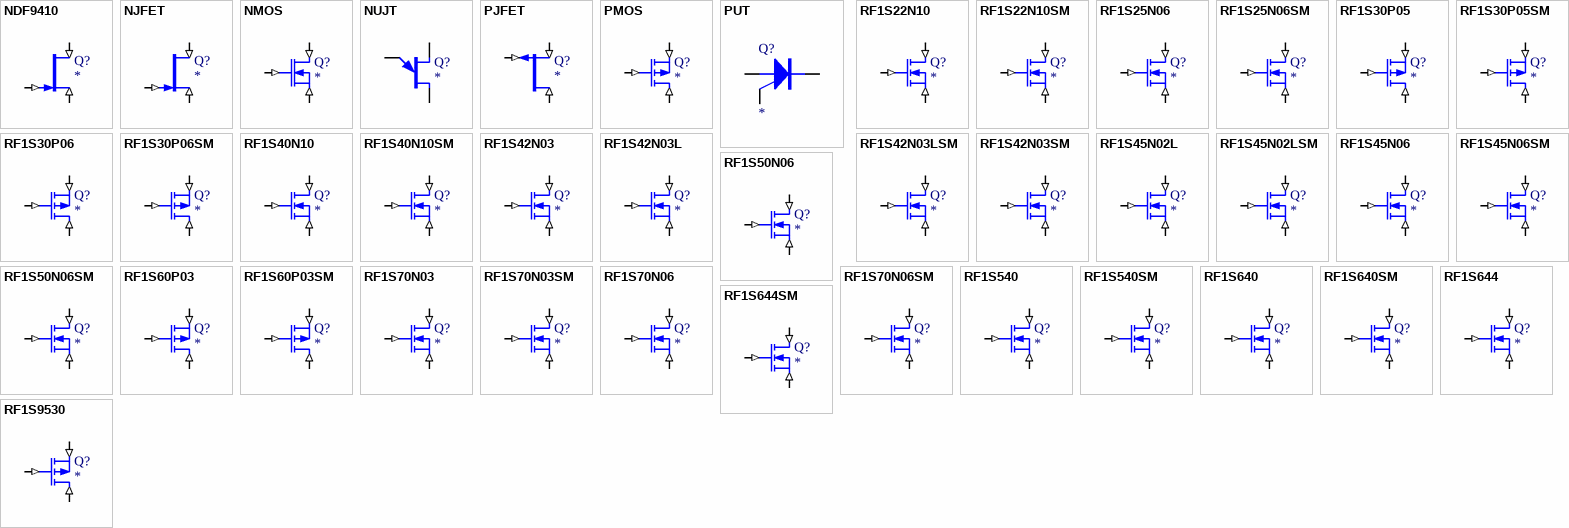
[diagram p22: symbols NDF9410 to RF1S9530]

## NDF9410
designator Q?
N-Channel JFET
simulation model NDF9410 (NJFET)
pins: 1 D (in), 2 G (in), 3 S (in)
1 alternate drawing of the same symbol

## NJFET
designator Q?
N-Channel JFET
simulation model NJFET
pins: 1 D (in), 2 G (in), 3 S (in)
1 alternate drawing of the same symbol

## NMOS
designator Q?
N-Channel MOSFET
simulation model NMOS (NEMOS)
pins: 1 D (in), 2 G (in), 3 S (in)
1 alternate drawing of the same symbol

## NUJT
designator Q?
Unijunction Transistor
simulation model NUJT (SUBCKT)
pins: 1 B2, 2 E, 3 B1
1 alternate drawing of the same symbol

## PJFET
designator Q?
P-Channel JFET
simulation model PJFET
pins: 1 D (in), 2 G (in), 3 S (in)
1 alternate drawing of the same symbol

## PMOS
designator Q?
P-Channel MOSFET
simulation model PMOS (PEMOS)
pins: 1 D (in), 2 G (in), 3 S (in)
1 alternate drawing of the same symbol

## PUT
designator Q?
Programmable Unijunction Transistor
simulation model PUT (SUBCKT)
pins: 1 A, 2 G, 3 K
1 alternate drawing of the same symbol

## RF1S22N10
designator Q?
N-Channel MOSFET
simulation model RF1S22N10 (SUBCKT)
pins: 1 D (in), 2 G (in), 3 S (in)
1 alternate drawing of the same symbol

## RF1S22N10SM
designator Q?
N-Channel MOSFET
simulation model RF1S22N10SM (SUBCKT)
pins: 1 D (in), 2 G (in), 3 S (in)
1 alternate drawing of the same symbol

## RF1S25N06
designator Q?
N-Channel MOSFET
simulation model RF1S25N06 (SUBCKT)
pins: 1 D (in), 2 G (in), 3 S (in)
1 alternate drawing of the same symbol

## RF1S25N06SM
designator Q?
N-Channel MOSFET
simulation model RF1S25N06SM (SUBCKT)
pins: 1 D (in), 2 G (in), 3 S (in)
1 alternate drawing of the same symbol

## RF1S30P05
designator Q?
P-Channel MOSFET
simulation model RF1S30P05 (SUBCKT)
pins: 1 D (in), 2 G (in), 3 S (in)
1 alternate drawing of the same symbol

## RF1S30P05SM
designator Q?
P-Channel MOSFET
simulation model RF1S30P05SM (SUBCKT)
pins: 1 D (in), 2 G (in), 3 S (in)
1 alternate drawing of the same symbol

## RF1S30P06
designator Q?
P-Channel MOSFET
simulation model RF1S30P06 (SUBCKT)
pins: 1 D (in), 2 G (in), 3 S (in)
1 alternate drawing of the same symbol

## RF1S30P06SM
designator Q?
P-Channel MOSFET
simulation model RF1S30P06SM (SUBCKT)
pins: 1 D (in), 2 G (in), 3 S (in)
1 alternate drawing of the same symbol

## RF1S40N10
designator Q?
N-Channel MOSFET
simulation model RF1S40N10 (SUBCKT)
pins: 1 D (in), 2 G (in), 3 S (in)
1 alternate drawing of the same symbol

## RF1S40N10SM
designator Q?
N-Channel MOSFET
simulation model RF1S40N10SM (SUBCKT)
pins: 1 D (in), 2 G (in), 3 S (in)
1 alternate drawing of the same symbol

## RF1S42N03
designator Q?
N-Channel MOSFET
simulation model RF1S42N03 (SUBCKT)
pins: 1 D (in), 2 G (in), 3 S (in)
1 alternate drawing of the same symbol

## RF1S42N03L
designator Q?
N-Channel MOSFET
simulation model RF1S42N03L (SUBCKT)
pins: 1 D (in), 2 G (in), 3 S (in)
1 alternate drawing of the same symbol

## RF1S42N03LSM
designator Q?
N-Channel MOSFET
simulation model RF1S42N03LSM (SUBCKT)
pins: 1 D (in), 2 G (in), 3 S (in)
1 alternate drawing of the same symbol

## RF1S42N03SM
designator Q?
N-Channel MOSFET
simulation model RF1S42N03SM (SUBCKT)
pins: 1 D (in), 2 G (in), 3 S (in)
1 alternate drawing of the same symbol

## RF1S45N02L
designator Q?
N-Channel MOSFET
simulation model RF1S45N02L (SUBCKT)
pins: 1 D (in), 2 G (in), 3 S (in)
1 alternate drawing of the same symbol

## RF1S45N02LSM
designator Q?
N-Channel MOSFET
simulation model RF1S45N02LSM (SUBCKT)
pins: 1 D (in), 2 G (in), 3 S (in)
1 alternate drawing of the same symbol

## RF1S45N06
designator Q?
N-Channel MOSFET
simulation model RF1S45N06 (SUBCKT)
pins: 1 D (in), 2 G (in), 3 S (in)
1 alternate drawing of the same symbol

## RF1S45N06SM
designator Q?
N-Channel MOSFET
simulation model RF1S45N06SM (SUBCKT)
pins: 1 D (in), 2 G (in), 3 S (in)
1 alternate drawing of the same symbol

## RF1S50N06
designator Q?
N-Channel MOSFET
simulation model RF1S50N06 (SUBCKT)
pins: 1 D (in), 2 G (in), 3 S (in)
1 alternate drawing of the same symbol

## RF1S50N06SM
designator Q?
N-Channel MOSFET
simulation model RF1S50N06SM (SUBCKT)
pins: 1 D (in), 2 G (in), 3 S (in)
1 alternate drawing of the same symbol

## RF1S60P03
designator Q?
P-Channel MOSFET
simulation model RF1S60P03 (SUBCKT)
pins: 1 D (in), 2 G (in), 3 S (in)
1 alternate drawing of the same symbol

## RF1S60P03SM
designator Q?
P-Channel MOSFET
simulation model RF1S60P03SM (SUBCKT)
pins: 1 D (in), 2 G (in), 3 S (in)
1 alternate drawing of the same symbol

## RF1S70N03
designator Q?
N-Channel MOSFET
simulation model RF1S70N03 (SUBCKT)
pins: 1 D (in), 2 G (in), 3 S (in)
1 alternate drawing of the same symbol

## RF1S70N03SM
designator Q?
N-Channel MOSFET
simulation model RF1S70N03SM (SUBCKT)
pins: 1 D (in), 2 G (in), 3 S (in)
1 alternate drawing of the same symbol

## RF1S70N06
designator Q?
N-Channel MOSFET
simulation model RF1S70N06 (SUBCKT)
pins: 1 D (in), 2 G (in), 3 S (in)
1 alternate drawing of the same symbol

## RF1S70N06SM
designator Q?
N-Channel MOSFET
simulation model RF1S70N06SM (SUBCKT)
pins: 1 D (in), 2 G (in), 3 S (in)
1 alternate drawing of the same symbol

## RF1S540
designator Q?
N-Channel MOSFET
simulation model RF1S540 (SUBCKT)
pins: 1 D (in), 2 G (in), 3 S (in)
1 alternate drawing of the same symbol

## RF1S540SM
designator Q?
N-Channel MOSFET
simulation model RF1S540SM (SUBCKT)
pins: 1 D (in), 2 G (in), 3 S (in)
1 alternate drawing of the same symbol

## RF1S640
designator Q?
N-Channel MOSFET
simulation model RF1S640 (SUBCKT)
pins: 1 D (in), 2 G (in), 3 S (in)
1 alternate drawing of the same symbol

## RF1S640SM
designator Q?
N-Channel MOSFET
simulation model RF1S640SM (SUBCKT)
pins: 1 D (in), 2 G (in), 3 S (in)
1 alternate drawing of the same symbol

## RF1S644
designator Q?
N-Channel MOSFET
simulation model RF1S644 (SUBCKT)
pins: 1 D (in), 2 G (in), 3 S (in)
1 alternate drawing of the same symbol

## RF1S644SM
designator Q?
N-Channel MOSFET
simulation model RF1S644SM (SUBCKT)
pins: 1 D (in), 2 G (in), 3 S (in)
1 alternate drawing of the same symbol

## RF1S9530
designator Q?
P-Channel MOSFET
simulation model RF1S9530 (SUBCKT)
pins: 1 D (in), 2 G (in), 3 S (in)
1 alternate drawing of the same symbol

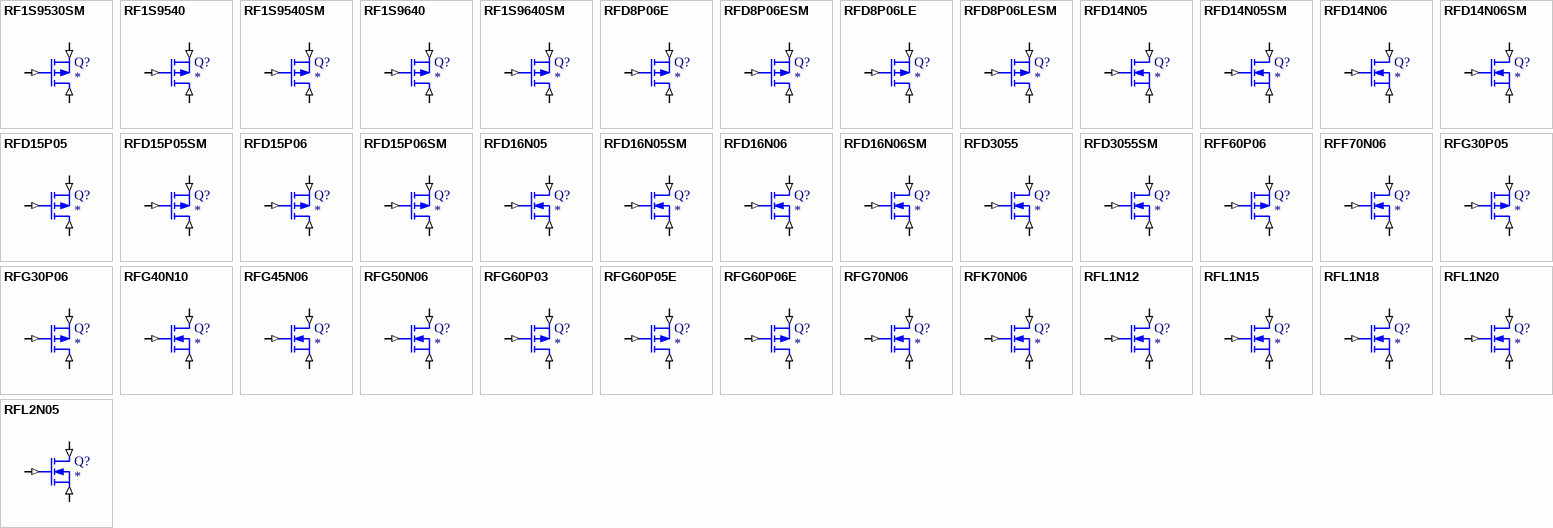
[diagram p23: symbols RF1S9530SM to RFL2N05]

## RF1S9530SM
designator Q?
P-Channel MOSFET
simulation model RF1S9530SM (SUBCKT)
pins: 1 D (in), 2 G (in), 3 S (in)
1 alternate drawing of the same symbol

## RF1S9540
designator Q?
P-Channel MOSFET
simulation model RF1S9540 (SUBCKT)
pins: 1 D (in), 2 G (in), 3 S (in)
1 alternate drawing of the same symbol

## RF1S9540SM
designator Q?
P-Channel MOSFET
simulation model RF1S9540SM (SUBCKT)
pins: 1 D (in), 2 G (in), 3 S (in)
1 alternate drawing of the same symbol

## RF1S9640
designator Q?
P-Channel MOSFET
simulation model RF1S9640 (SUBCKT)
pins: 1 D (in), 2 G (in), 3 S (in)
1 alternate drawing of the same symbol

## RF1S9640SM
designator Q?
P-Channel MOSFET
simulation model RF1S9640SM (SUBCKT)
pins: 1 D (in), 2 G (in), 3 S (in)
1 alternate drawing of the same symbol

## RFD8P06E
designator Q?
P-Channel MOSFET
simulation model RFD8P06E (SUBCKT)
pins: 1 D (in), 2 G (in), 3 S (in)
1 alternate drawing of the same symbol

## RFD8P06ESM
designator Q?
P-Channel MOSFET
simulation model RFD8P06ESM (SUBCKT)
pins: 1 D (in), 2 G (in), 3 S (in)
1 alternate drawing of the same symbol

## RFD8P06LE
designator Q?
P-Channel MOSFET
simulation model RFD8P06LE (SUBCKT)
pins: 1 D (in), 2 G (in), 3 S (in)
1 alternate drawing of the same symbol

## RFD8P06LESM
designator Q?
P-Channel MOSFET
simulation model RFD8P06LESM (SUBCKT)
pins: 1 D (in), 2 G (in), 3 S (in)
1 alternate drawing of the same symbol

## RFD14N05
designator Q?
N-Channel MOSFET
simulation model RFD14N05 (SUBCKT)
pins: 1 D (in), 2 G (in), 3 S (in)
1 alternate drawing of the same symbol

## RFD14N05SM
designator Q?
N-Channel MOSFET
simulation model RFD14N05SM (SUBCKT)
pins: 1 D (in), 2 G (in), 3 S (in)
1 alternate drawing of the same symbol

## RFD14N06
designator Q?
N-Channel MOSFET
simulation model RFD14N06 (SUBCKT)
pins: 1 D (in), 2 G (in), 3 S (in)
1 alternate drawing of the same symbol

## RFD14N06SM
designator Q?
N-Channel MOSFET
simulation model RFD14N06SM (SUBCKT)
pins: 1 D (in), 2 G (in), 3 S (in)
1 alternate drawing of the same symbol

## RFD15P05
designator Q?
P-Channel MOSFET
simulation model RFD15P05 (SUBCKT)
pins: 1 D (in), 2 G (in), 3 S (in)
1 alternate drawing of the same symbol

## RFD15P05SM
designator Q?
P-Channel MOSFET
simulation model RFD15P05SM (SUBCKT)
pins: 1 D (in), 2 G (in), 3 S (in)
1 alternate drawing of the same symbol

## RFD15P06
designator Q?
P-Channel MOSFET
simulation model RFD15P06 (SUBCKT)
pins: 1 D (in), 2 G (in), 3 S (in)
1 alternate drawing of the same symbol

## RFD15P06SM
designator Q?
P-Channel MOSFET
simulation model RFD15P06SM (SUBCKT)
pins: 1 D (in), 2 G (in), 3 S (in)
1 alternate drawing of the same symbol

## RFD16N05
designator Q?
N-Channel MOSFET
simulation model RFD16N05 (SUBCKT)
pins: 1 D (in), 2 G (in), 3 S (in)
1 alternate drawing of the same symbol

## RFD16N05SM
designator Q?
N-Channel MOSFET
simulation model RFD16N05SM (SUBCKT)
pins: 1 D (in), 2 G (in), 3 S (in)
1 alternate drawing of the same symbol

## RFD16N06
designator Q?
N-Channel MOSFET
simulation model RFD16N06 (SUBCKT)
pins: 1 D (in), 2 G (in), 3 S (in)
1 alternate drawing of the same symbol

## RFD16N06SM
designator Q?
N-Channel MOSFET
simulation model RFD16N06SM (SUBCKT)
pins: 1 D (in), 2 G (in), 3 S (in)
1 alternate drawing of the same symbol

## RFD3055
designator Q?
N-Channel MOSFET
simulation model RFD3055 (SUBCKT)
pins: 1 D (in), 2 G (in), 3 S (in)
1 alternate drawing of the same symbol

## RFD3055SM
designator Q?
N-Channel MOSFET
simulation model RFD3055SM (SUBCKT)
pins: 1 D (in), 2 G (in), 3 S (in)
1 alternate drawing of the same symbol

## RFF60P06
designator Q?
P-Channel MOSFET
simulation model RFF60P06 (SUBCKT)
pins: 1 D (in), 2 G (in), 3 S (in)
1 alternate drawing of the same symbol

## RFF70N06
designator Q?
N-Channel MOSFET
simulation model RFF70N06 (SUBCKT)
pins: 1 D (in), 2 G (in), 3 S (in)
1 alternate drawing of the same symbol

## RFG30P05
designator Q?
P-Channel MOSFET
simulation model RFG30P05 (SUBCKT)
pins: 1 D (in), 2 G (in), 3 S (in)
1 alternate drawing of the same symbol

## RFG30P06
designator Q?
P-Channel MOSFET
simulation model RFG30P06 (SUBCKT)
pins: 1 D (in), 2 G (in), 3 S (in)
1 alternate drawing of the same symbol

## RFG40N10
designator Q?
N-Channel MOSFET
simulation model RFG40N10 (SUBCKT)
pins: 1 D (in), 2 G (in), 3 S (in)
1 alternate drawing of the same symbol

## RFG45N06
designator Q?
N-Channel MOSFET
simulation model RFG45N06 (SUBCKT)
pins: 1 D (in), 2 G (in), 3 S (in)
1 alternate drawing of the same symbol

## RFG50N06
designator Q?
N-Channel MOSFET
simulation model RFG50N06 (SUBCKT)
pins: 1 D (in), 2 G (in), 3 S (in)
1 alternate drawing of the same symbol

## RFG60P03
designator Q?
P-Channel MOSFET
simulation model RFG60P03 (SUBCKT)
pins: 1 D (in), 2 G (in), 3 S (in)
1 alternate drawing of the same symbol

## RFG60P05E
designator Q?
P-Channel MOSFET
simulation model RFG60P05E (SUBCKT)
pins: 1 D (in), 2 G (in), 3 S (in)
1 alternate drawing of the same symbol

## RFG60P06E
designator Q?
P-Channel MOSFET
simulation model RFG60P06E (SUBCKT)
pins: 1 D (in), 2 G (in), 3 S (in)
1 alternate drawing of the same symbol

## RFG70N06
designator Q?
N-Channel MOSFET
simulation model RFG70N06 (SUBCKT)
pins: 1 D (in), 2 G (in), 3 S (in)
1 alternate drawing of the same symbol

## RFK70N06
designator Q?
N-Channel MOSFET
simulation model RFK70N06 (SUBCKT)
pins: 1 D (in), 2 G (in), 3 S (in)
1 alternate drawing of the same symbol

## RFL1N12
designator Q?
N-Channel MOSFET
simulation model RFL1N12 (SUBCKT)
pins: 1 D (in), 2 G (in), 3 S (in)
1 alternate drawing of the same symbol

## RFL1N15
designator Q?
N-Channel MOSFET
simulation model RFL1N15 (SUBCKT)
pins: 1 D (in), 2 G (in), 3 S (in)
1 alternate drawing of the same symbol

## RFL1N18
designator Q?
N-Channel MOSFET
simulation model RFL1N18 (SUBCKT)
pins: 1 D (in), 2 G (in), 3 S (in)
1 alternate drawing of the same symbol

## RFL1N20
designator Q?
N-Channel MOSFET
simulation model RFL1N20 (SUBCKT)
pins: 1 D (in), 2 G (in), 3 S (in)
1 alternate drawing of the same symbol

## RFL2N05
designator Q?
N-Channel MOSFET
simulation model RFL2N05 (SUBCKT)
pins: 1 D (in), 2 G (in), 3 S (in)
1 alternate drawing of the same symbol

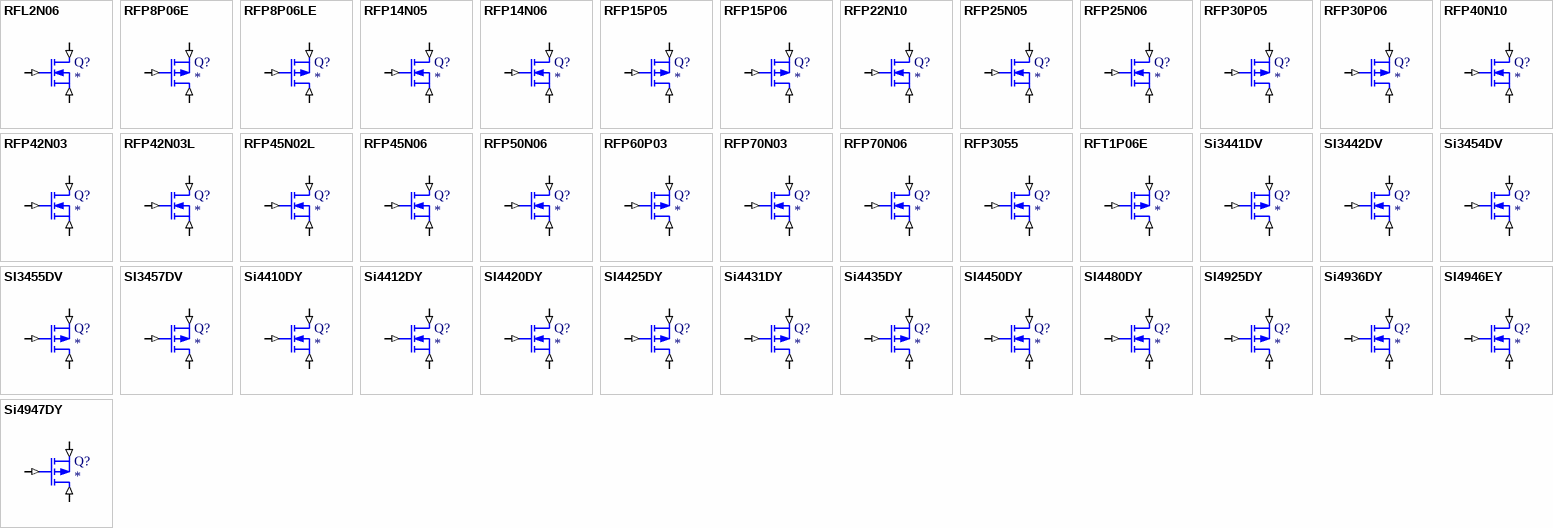
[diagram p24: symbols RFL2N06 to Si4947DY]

## RFL2N06
designator Q?
N-Channel MOSFET
simulation model RFL2N06 (SUBCKT)
pins: 1 D (in), 2 G (in), 3 S (in)
1 alternate drawing of the same symbol

## RFP8P06E
designator Q?
P-Channel MOSFET
simulation model RFP8P06E (SUBCKT)
pins: 1 D (in), 2 G (in), 3 S (in)
1 alternate drawing of the same symbol

## RFP8P06LE
designator Q?
P-Channel MOSFET
simulation model RFP8P06LE (SUBCKT)
pins: 1 D (in), 2 G (in), 3 S (in)
1 alternate drawing of the same symbol

## RFP14N05
designator Q?
N-Channel MOSFET
simulation model RFP14N05 (SUBCKT)
pins: 1 D (in), 2 G (in), 3 S (in)
1 alternate drawing of the same symbol

## RFP14N06
designator Q?
N-Channel MOSFET
simulation model RFP14N06 (SUBCKT)
pins: 1 D (in), 2 G (in), 3 S (in)
1 alternate drawing of the same symbol

## RFP15P05
designator Q?
P-Channel MOSFET
simulation model RFP15P05 (SUBCKT)
pins: 1 D (in), 2 G (in), 3 S (in)
1 alternate drawing of the same symbol

## RFP15P06
designator Q?
P-Channel MOSFET
simulation model RFP15P06 (SUBCKT)
pins: 1 D (in), 2 G (in), 3 S (in)
1 alternate drawing of the same symbol

## RFP22N10
designator Q?
N-Channel MOSFET
simulation model RFP22N10 (SUBCKT)
pins: 1 D (in), 2 G (in), 3 S (in)
1 alternate drawing of the same symbol

## RFP25N05
designator Q?
N-Channel MOSFET
simulation model RFP25N05 (SUBCKT)
pins: 1 D (in), 2 G (in), 3 S (in)
1 alternate drawing of the same symbol

## RFP25N06
designator Q?
N-Channel MOSFET
simulation model RFP25N06 (SUBCKT)
pins: 1 D (in), 2 G (in), 3 S (in)
1 alternate drawing of the same symbol

## RFP30P05
designator Q?
P-Channel MOSFET
simulation model RFP30P05 (SUBCKT)
pins: 1 D (in), 2 G (in), 3 S (in)
1 alternate drawing of the same symbol

## RFP30P06
designator Q?
P-Channel MOSFET
simulation model RFP30P06 (SUBCKT)
pins: 1 D (in), 2 G (in), 3 S (in)
1 alternate drawing of the same symbol

## RFP40N10
designator Q?
N-Channel MOSFET
simulation model RFP40N10 (SUBCKT)
pins: 1 D (in), 2 G (in), 3 S (in)
1 alternate drawing of the same symbol

## RFP42N03
designator Q?
N-Channel MOSFET
simulation model RFP42N03 (SUBCKT)
pins: 1 D (in), 2 G (in), 3 S (in)
1 alternate drawing of the same symbol

## RFP42N03L
designator Q?
N-Channel MOSFET
simulation model RFP42N03L (SUBCKT)
pins: 1 D (in), 2 G (in), 3 S (in)
1 alternate drawing of the same symbol

## RFP45N02L
designator Q?
N-Channel MOSFET
simulation model RFP45N02L (SUBCKT)
pins: 1 D (in), 2 G (in), 3 S (in)
1 alternate drawing of the same symbol

## RFP45N06
designator Q?
N-Channel MOSFET
simulation model RFP45N06 (SUBCKT)
pins: 1 D (in), 2 G (in), 3 S (in)
1 alternate drawing of the same symbol

## RFP50N06
designator Q?
N-Channel MOSFET
simulation model RFP50N06 (SUBCKT)
pins: 1 D (in), 2 G (in), 3 S (in)
1 alternate drawing of the same symbol

## RFP60P03
designator Q?
P-Channel MOSFET
simulation model RFP60P03 (SUBCKT)
pins: 1 D (in), 2 G (in), 3 S (in)
1 alternate drawing of the same symbol

## RFP70N03
designator Q?
N-Channel MOSFET
simulation model RFP70N03 (SUBCKT)
pins: 1 D (in), 2 G (in), 3 S (in)
1 alternate drawing of the same symbol

## RFP70N06
designator Q?
N-Channel MOSFET
simulation model RFP70N06 (SUBCKT)
pins: 1 D (in), 2 G (in), 3 S (in)
1 alternate drawing of the same symbol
